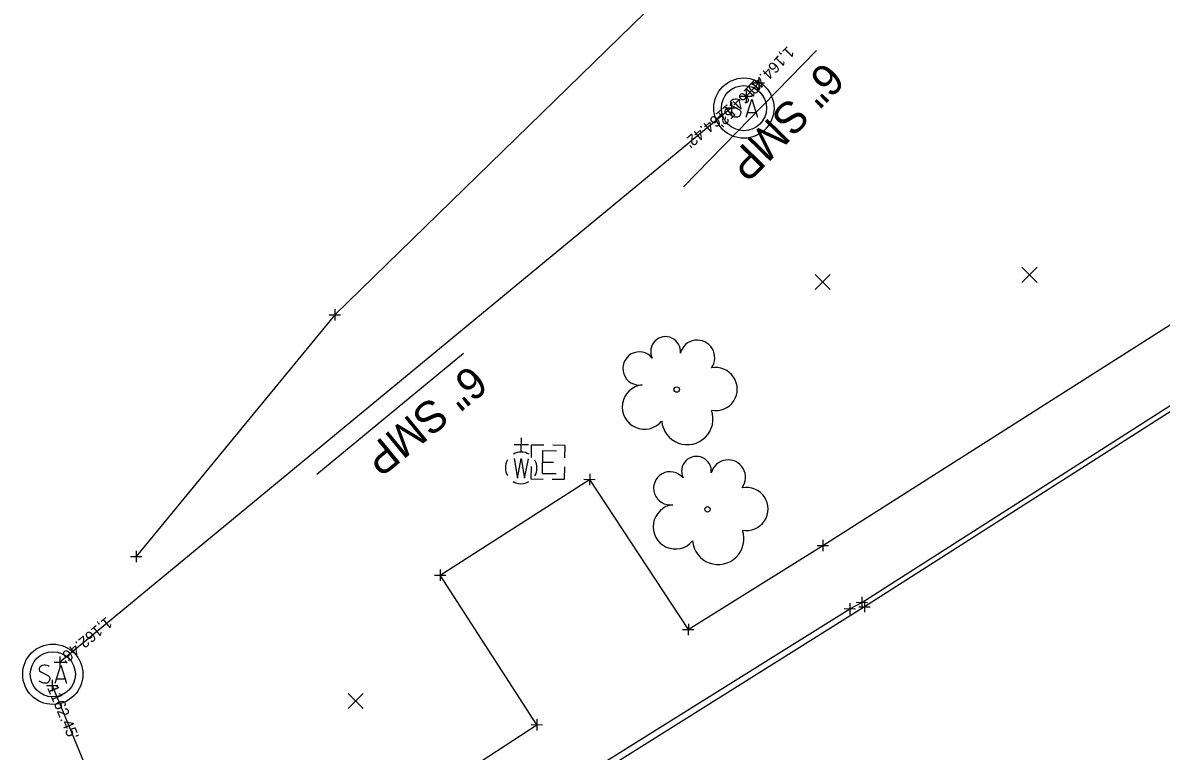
# Model space of a CAD drawing. Extents: x 142461 to 147261, y 511126 to 514697.
# Drawn here: x 145180.3 to 145281.3, y 513693.8 to 513758.4 of the extents above; entities that cross this region are included whole.
import ezdxf

# ---------------------------------------------------------------- set-up
doc = ezdxf.new("R2010")
doc.units = 0
for name, color, linetype in [('DR_X_Text', 7, 'Continuous'), ('GK_Drainage_Nodes', 7, 'Continuous'), ('PV_X_Curb', 7, 'Continuous'), ('PV_X_EOP', 7, 'Continuous'), ('PV_X_Walk', 7, 'Continuous'), ('SC_Scratch1', 7, 'Continuous'), ('SV_X_Random_Point', 7, 'Continuous'), ('SV_X_Shot_Marker', 7, 'Continuous'), ('SV_X_Top_of_Bank', 7, 'Continuous'), ('UT_X_Electric_Cells', 7, 'Continuous'), ('UT_X_Sanitary_Cells', 7, 'Continuous'), ('UT_X_Sanitary_Line', 7, 'Continuous'), ('UT_X_Sanitary_Text', 7, 'Continuous'), ('UT_X_Water_Cells', 7, 'Continuous'), ('VG_X_Cells', 7, 'Continuous')]:
    doc.layers.add(name, color=color, linetype=linetype)

msp = doc.modelspace()

# ---------------------------------------------------------------- linework, layer by layer
at = {"layer": 'DR_X_Text'}
msp.add_line((145206.42, 513718.36), (145219.44, 513729.09), dxfattribs=at)
at = {"layer": 'GK_Drainage_Nodes'}
for p, q in [((145244.31, 513752.81), (145244.31, 513752.81)), ((145244.31, 513750.81), (145244.31, 513750.81)), ((145244.31, 513750.81), (145244.31, 513750.81)), ((145244.31, 513750.81), (145244.31, 513750.81)), ((145244.31, 513748.81), (145244.31, 513748.81)), ((145183.01, 513702.64), (145183.01, 513702.64)), ((145183.01, 513700.64), (145183.01, 513700.64)), ((145183.01, 513700.64), (145183.01, 513700.64)), ((145183.01, 513700.64), (145183.01, 513700.64)), ((145183.01, 513698.64), (145183.01, 513698.64))]:
    msp.add_line(p, q, dxfattribs=at)
for centre in [(145244.31, 513750.81), (145183.01, 513700.64)]:
    msp.add_circle(centre, 2, dxfattribs=at)
at = {"layer": 'PV_X_Curb'}
msp.add_lwpolyline([(145227.69, 513660.65), (145214.65, 513681.65), (145226.59, 513689.4), (145227.71, 513690.22), (145253.7, 513706.45), (145254.76, 513707.01), (145306.51, 513740.01), (145357, 513772.11), (145410.28, 513806.15), (145439.46, 513824.75), (145448.27, 513830.42), (145452.54, 513833.13), (145456.82, 513835.85), (145503.2, 513865.44), (145542.33, 513890.92), (145551.43, 513885.04), (145559.02, 513886.59), (145559.54, 513886.77)], dxfattribs=at)
at = {"layer": 'PV_X_EOP'}
for p, q in [((145306.74, 513739.62), (145255.01, 513706.63)), ((145255.01, 513706.63), (145226.82, 513688.97))]:
    msp.add_line(p, q, dxfattribs=at)
at = {"layer": 'PV_X_Walk'}
for p, q in [((145251.3, 513712.06), (145303.28, 513745.08)), ((145217.37, 513709.42), (145230.62, 513717.91)), ((145230.62, 513717.91), (145239.37, 513704.61)), ((145239.37, 513704.61), (145251.3, 513712.06)), ((145225.94, 513696.17), (145217.37, 513709.42)), ((145216.26, 513689.85), (145225.94, 513696.17))]:
    msp.add_line(p, q, dxfattribs=at)
at = {"layer": 'SV_X_Random_Point'}
for p, q in [((145268.97, 513735.37), (145270.31, 513736.71)), ((145268.97, 513736.71), (145270.31, 513735.37)), ((145250.64, 513734.75), (145251.97, 513736.08)), ((145250.64, 513736.08), (145251.97, 513734.75)), ((145209.2, 513697.6), (145210.54, 513698.94)), ((145209.2, 513698.94), (145210.54, 513697.6))]:
    msp.add_line(p, q, dxfattribs=at)
at = {"layer": 'SV_X_Shot_Marker'}
for p, q in [((145245.13, 513753.04), (145246.13, 513753.04)), ((145245.63, 513753.54), (145245.63, 513752.54)), ((145245.63, 513753.04), (145245.63, 513753.04)), ((145244, 513751.88), (145245, 513751.88)), ((145244.5, 513752.38), (145244.5, 513751.38)), ((145244.5, 513751.88), (145244.5, 513751.88)), ((145242.71, 513750.83), (145243.71, 513750.83)), ((145243.21, 513751.33), (145243.21, 513750.33)), ((145243.21, 513750.83), (145243.21, 513750.83)), ((145208.02, 513733), (145208.02, 513732)), ((145207.52, 513732.5), (145208.52, 513732.5)), ((145208.02, 513732.5), (145208.02, 513732.5)), ((145230.12, 513717.92), (145231.12, 513717.9)), ((145230.63, 513718.41), (145230.62, 513717.41)), ((145230.62, 513717.91), (145230.62, 513717.91)), ((145251.31, 513712.56), (145251.3, 513711.56)), ((145190.41, 513711.57), (145190.41, 513710.57)), ((145250.8, 513712.06), (145251.8, 513712.05)), ((145251.3, 513712.06), (145251.3, 513712.06)), ((145189.91, 513711.07), (145190.91, 513711.07)), ((145190.41, 513711.07), (145190.41, 513711.07)), ((145216.87, 513709.43), (145217.87, 513709.42)), ((145217.38, 513709.92), (145217.37, 513708.92)), ((145217.37, 513709.42), (145217.37, 513709.42)), ((145254.77, 513707.51), (145254.76, 513706.51)), ((145253.2, 513706.46), (145254.2, 513706.45)), ((145253.7, 513706.95), (145253.69, 513705.95)), ((145253.7, 513706.45), (145253.7, 513706.45)), ((145254.26, 513707.02), (145255.26, 513707.01)), ((145254.51, 513706.63), (145255.51, 513706.62)), ((145254.76, 513707.01), (145254.76, 513707.01)), ((145255.02, 513707.13), (145255.01, 513706.13)), ((145255.01, 513706.63), (145255.01, 513706.63)), ((145238.87, 513704.61), (145239.87, 513704.6)), ((145239.38, 513705.11), (145239.37, 513704.11)), ((145239.37, 513704.61), (145239.37, 513704.61)), ((145183.13, 513701.72), (145184.13, 513701.72)), ((145183.63, 513702.22), (145183.63, 513701.22)), ((145183.63, 513701.72), (145183.63, 513701.72)), ((145182.45, 513699.65), (145183.45, 513699.65)), ((145182.95, 513700.15), (145182.95, 513699.15)), ((145182.95, 513699.65), (145182.95, 513699.65)), ((145225.94, 513696.67), (145225.93, 513695.67)), ((145225.44, 513696.18), (145226.44, 513696.17)), ((145225.94, 513696.17), (145225.94, 513696.17))]:
    msp.add_line(p, q, dxfattribs=at)
at = {"layer": 'SV_X_Top_of_Bank'}
msp.add_lwpolyline([(145321.84, 513854.3), (145286.21, 513815.76), (145251.63, 513774.97), (145208.02, 513732.5), (145190.41, 513711.07)], dxfattribs=at)
at = {"layer": 'UT_X_Electric_Cells'}
for p, q in [((145226.43, 513719.44), (145227.43, 513719.43)), ((145226.93, 513719.43), (145226.93, 513719.43))]:
    msp.add_line(p, q, dxfattribs=at)
for points in [[(145226.55, 513720.94), (145225.45, 513720.95), (145225.43, 513719.85)], [(145228.43, 513719.82), (145228.45, 513720.92), (145227.35, 513720.93)], [(145227.69, 513720.42), (145226.44, 513720.44), (145226.42, 513718.44), (145227.67, 513718.42)], [(145225.43, 513719.05), (145225.41, 513717.95), (145226.51, 513717.94)], [(145227.31, 513717.93), (145228.41, 513717.92), (145228.43, 513719.02)]]:
    msp.add_lwpolyline(points, dxfattribs=at)
at = {"layer": 'UT_X_Sanitary_Cells'}
for points in [[(145243.97, 513751.49), (145243.95, 513751.52), (145243.91, 513751.54), (145243.8, 513751.58), (145243.66, 513751.61), (145243.56, 513751.61), (145243.52, 513751.61), (145243.36, 513751.57), (145243.22, 513751.49), (145243.13, 513751.39), (145243.11, 513751.29), (145243.11, 513751.21), (145243.13, 513751.11), (145243.23, 513751.03), (145243.92, 513750.65), (145243.99, 513750.6), (145244.01, 513750.55), (145244.04, 513750.47), (145244.04, 513750.4), (145244.02, 513750.32), (145244.01, 513750.27), (145243.99, 513750.21), (145243.96, 513750.16), (145243.94, 513750.12), (145243.9, 513750.08), (145243.86, 513750.06), (145243.81, 513750.03), (145243.77, 513750.02), (145243.66, 513750.01), (145243.48, 513750.01), (145243.37, 513750.03), (145243.21, 513750.12), (145243.11, 513750.19)], [(145244.52, 513750.01), (145245.02, 513751.61), (145245.51, 513750.01)], [(145245.39, 513750.38), (145244.64, 513750.38)], [(145182.68, 513701.33), (145182.66, 513701.36), (145182.62, 513701.38), (145182.5, 513701.42), (145182.37, 513701.44), (145182.26, 513701.44), (145182.23, 513701.44), (145182.06, 513701.41), (145181.92, 513701.33), (145181.84, 513701.23), (145181.81, 513701.13), (145181.81, 513701.05), (145181.84, 513700.95), (145181.94, 513700.86), (145182.63, 513700.49), (145182.69, 513700.44), (145182.72, 513700.39), (145182.74, 513700.31), (145182.74, 513700.23), (145182.73, 513700.16), (145182.72, 513700.11), (145182.69, 513700.05), (145182.67, 513700), (145182.64, 513699.96), (145182.6, 513699.92), (145182.57, 513699.89), (145182.52, 513699.87), (145182.48, 513699.86), (145182.37, 513699.84), (145182.19, 513699.84), (145182.08, 513699.87), (145181.91, 513699.96), (145181.81, 513700.03)], [(145183.22, 513699.84), (145183.73, 513701.44), (145184.22, 513699.84)], [(145184.09, 513700.22), (145183.35, 513700.22)]]:
    msp.add_lwpolyline(points, dxfattribs=at)
for centre, radius in [((145244.31, 513750.81), 2.67), ((145244.31, 513750.81), 2), ((145183.01, 513700.64), 2.67), ((145183.01, 513700.64), 2)]:
    msp.add_circle(centre, radius, dxfattribs=at)
at = {"layer": 'UT_X_Sanitary_Line'}
for p, q in [((145245.63, 513753.04), (145244.5, 513751.88)), ((145243.21, 513750.83), (145183.63, 513701.72)), ((145182.95, 513699.65), (145226.66, 513594.02))]:
    msp.add_line(p, q, dxfattribs=at)
at = {"layer": 'UT_X_Sanitary_Text'}
msp.add_line((145238.95, 513743.84), (145250.74, 513755.91), dxfattribs=at)
at = {"layer": 'UT_X_Water_Cells'}
for p, q in [((145224.56, 513720.33), (145224.58, 513721.6)), ((145225.2, 513720.96), (145223.93, 513720.97)), ((145224.55, 513718.93), (145224.55, 513718.93))]:
    msp.add_line(p, q, dxfattribs=at)
msp.add_lwpolyline([(145223.92, 513719.76), (145224.22, 513718.03), (145224.56, 513719.75), (145224.86, 513718.02), (145225.19, 513719.74)], dxfattribs=at)
for start, end in [(149.427, 209.3903), (59.427, 119.4244), (329.427, 29.3903), (239.3929, 299.3903)]:
    msp.add_arc((145224.55, 513718.93), 1.4, start, end, dxfattribs=at)
at = {"layer": 'VG_X_Cells'}
for centre in [(145238.35, 513725.87), (145241.08, 513715.26)]:
    msp.add_circle(centre, 0.24, dxfattribs=at)
for centre, radius, start, end in [((145237.36, 513729.24), 1.32, 354.0047, 205.9741), ((145240.17, 513728.7), 1.55, 323.83, 165.0376), ((145235.04, 513727.74), 1.47, 39.0625, 279.5412), ((145241.81, 513725.91), 1.91, 259.1453, 101.4596), ((145235.49, 513724.32), 1.97, 96.1722, 320.5737), ((145239.29, 513723.27), 2.28, 184.9476, 19.4572), ((145240.1, 513718.63), 1.32, 354.0047, 205.9741), ((145242.91, 513718.09), 1.55, 323.83, 165.0376), ((145237.77, 513717.12), 1.47, 39.0625, 279.5412), ((145244.54, 513715.29), 1.91, 259.1453, 101.4596), ((145238.23, 513713.71), 1.97, 96.1722, 320.5737), ((145242.03, 513712.65), 2.28, 184.9476, 19.4572)]:
    msp.add_arc(centre, radius, start, end, dxfattribs=at)

# ---------------------------------------------------------------- texts
at = {"layer": 'DR_X_Text'}
msp.add_text('6" SMP', height=2.8, rotation=219.5015, dxfattribs=at).set_placement((145220.05, 513728.17))
at = {"layer": 'SC_Scratch1'}
for s, rotation, p in [("1,164.40'", 225.677, (145248.18, 513756.36)), ("1164.52'", 225.677, (145245.27, 513753.38)), ("1164.42'", 219.5015, (145242.89, 513751.22)), ("1,162.46'", 219.5015, (145187.77, 513705.78)), ("1162.45'", 292.4779, (145182.49, 513699.46))]:
    msp.add_text(s, height=1, rotation=rotation, dxfattribs=at).set_placement(p)
at = {"layer": 'UT_X_Sanitary_Text'}
msp.add_text('6" SMP', height=2.8, rotation=225.677, dxfattribs=at).set_placement((145251.45, 513755.06))

doc.saveas('drawing.dxf')
